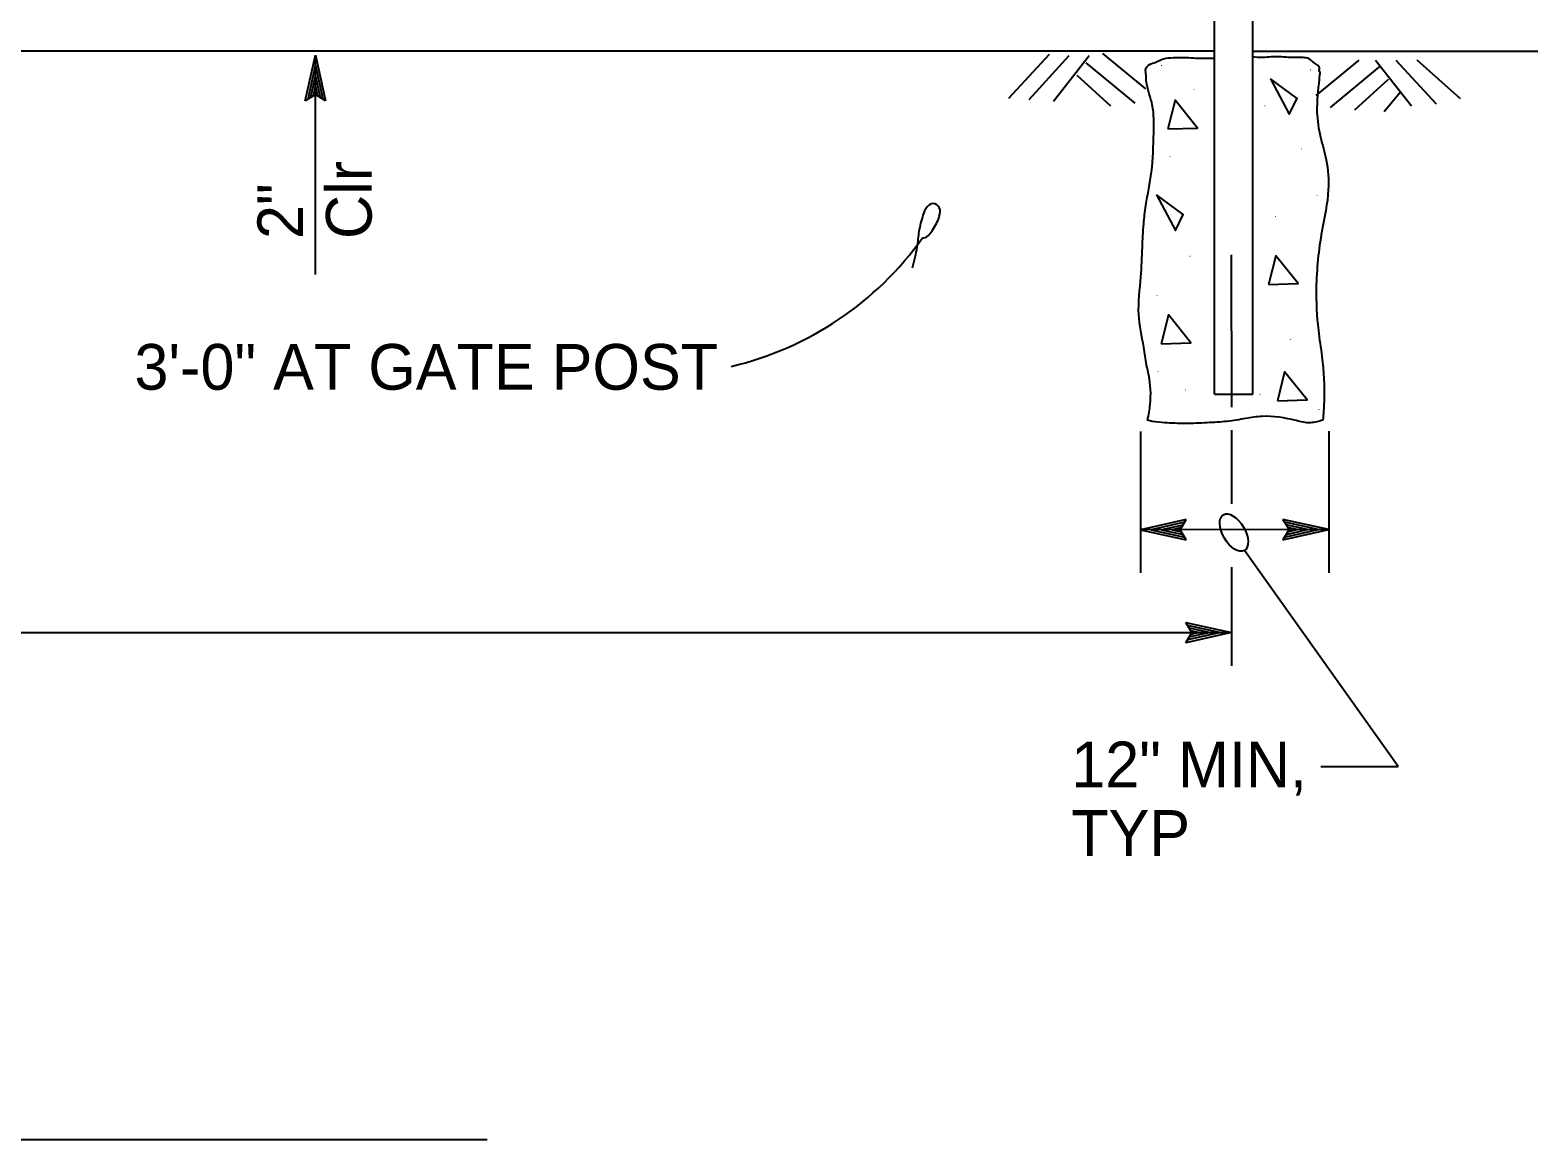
# Model space of a CAD drawing. Extents: x -121933 to -117742, y -103160 to -100084.
# Drawn here: x -120965.9 to -120768, y -102524.1 to -102378.5 of the extents above; entities that cross this region are included whole.
import ezdxf

# ---------------------------------------------------------------- set-up
doc = ezdxf.new("R2010")
doc.units = 0
for name, color, linetype in [('G-MARK', 7, 'Continuous'), ('G-TEXT', 7, 'Continuous'), ('Misc CnstDet(22)', 7, 'Continuous'), ('Nongeo Data(60)', 7, 'Continuous')]:
    doc.layers.add(name, color=color, linetype=linetype)

msp = doc.modelspace()

# ---------------------------------------------------------------- linework, layer by layer
at = {"layer": 'G-MARK'}
for p, q in [((-120928.4, -102410.53), (-120928.4, -102381.74)), ((-120820.14, -102431.16), (-120820.14, -102449.7)), ((-120795.42, -102431.12), (-120795.42, -102449.7)), ((-120795.42, -102444.03), (-120820.12, -102444.06)), ((-120786.31, -102475.15), (-120806.48, -102446.78)), ((-121220.62, -102457.55), (-120808.19, -102457.55)), ((-120796.44, -102475.15), (-120786.31, -102475.15))]:
    msp.add_line(p, q, dxfattribs=at)
for points in [[(-120808.21, -102407.98), (-120808.19, -102427.98)], [(-120808.19, -102430.98), (-120808.18, -102440.63)], [(-120808.18, -102448.96), (-120808.2, -102461.92)]]:
    msp.add_lwpolyline(points, dxfattribs=at)
msp.add_arc((-120883.78, -102380.7), 43.08, 283.3407, 324.4518, dxfattribs=at)
msp.add_ellipse((-120807.86, -102444.43), major_axis=(-1.38, 2.35), ratio=0.531478, dxfattribs=at)
msp.add_spline([(-120848.73, -102405.74), (-120848.4, -102405.69), (-120847.42, -102404.71), (-120846.53, -102402.93), (-120846.53, -102401.77), (-120847.33, -102401.24), (-120848.13, -102401.68), (-120848.67, -102402.75), (-120849.2, -102404.89), (-120849.47, -102406.94), (-120850.09, -102409.7)], degree=3, dxfattribs=at)
at = {"layer": 'G-TEXT'}
for p, q in [((-120929.74, -102387.74), (-120928.4, -102381.74)), ((-120929.38, -102387.53), (-120928.4, -102383.12)), ((-120928.4, -102381.74), (-120928.4, -102381.74)), ((-120928.4, -102381.74), (-120927.07, -102387.74)), ((-120928.4, -102383.13), (-120927.43, -102387.51)), ((-120929.02, -102387.29), (-120928.4, -102384.5)), ((-120928.4, -102384.5), (-120927.78, -102387.33)), ((-120928.4, -102386.94), (-120929.74, -102387.74)), ((-120928.68, -102387.12), (-120928.4, -102385.89)), ((-120928.4, -102385.89), (-120928.13, -102387.1)), ((-120927.07, -102387.74), (-120928.4, -102386.94)), ((-120929.74, -102387.74), (-120929.74, -102387.74)), ((-120927.07, -102387.74), (-120927.07, -102387.74)), ((-120814.12, -102442.71), (-120820.12, -102444.06)), ((-120820.12, -102444.06), (-120820.12, -102444.06)), ((-120820.12, -102444.06), (-120814.11, -102445.38)), ((-120814.33, -102443.07), (-120818.74, -102444.06)), ((-120818.72, -102444.06), (-120814.35, -102445.02)), ((-120814.57, -102443.43), (-120817.35, -102444.05)), ((-120817.35, -102444.05), (-120814.53, -102444.68)), ((-120814.74, -102443.77), (-120815.97, -102444.05)), ((-120815.97, -102444.05), (-120814.76, -102444.32)), ((-120814.92, -102444.05), (-120814.12, -102442.71)), ((-120814.11, -102445.38), (-120814.92, -102444.05)), ((-120814.12, -102442.71), (-120814.12, -102442.71)), ((-120795.42, -102444.03), (-120801.43, -102442.71)), ((-120801.43, -102442.71), (-120801.43, -102442.71)), ((-120801.43, -102442.71), (-120800.62, -102444.04)), ((-120801.42, -102445.38), (-120795.42, -102444.03)), ((-120800.62, -102444.04), (-120801.42, -102445.38)), ((-120801.21, -102445.02), (-120796.8, -102444.03)), ((-120796.82, -102444.03), (-120801.19, -102443.07)), ((-120798.19, -102444.04), (-120801.01, -102443.41)), ((-120800.97, -102444.66), (-120798.19, -102444.04)), ((-120800.8, -102444.32), (-120799.57, -102444.04)), ((-120799.57, -102444.04), (-120800.78, -102443.77)), ((-120795.42, -102444.03), (-120795.42, -102444.03)), ((-120814.11, -102445.38), (-120814.11, -102445.38)), ((-120801.42, -102445.38), (-120801.42, -102445.38)), ((-120813.39, -102457.55), (-120814.19, -102456.21)), ((-120814.19, -102456.21), (-120814.19, -102456.21)), ((-120814.19, -102456.21), (-120808.19, -102457.55)), ((-120808.19, -102457.55), (-120814.19, -102458.88)), ((-120814.19, -102458.88), (-120813.39, -102457.55)), ((-120813.98, -102456.57), (-120809.57, -102457.55)), ((-120809.58, -102457.55), (-120813.96, -102458.52)), ((-120810.95, -102457.55), (-120813.78, -102458.17)), ((-120813.74, -102456.93), (-120810.95, -102457.55)), ((-120813.57, -102457.27), (-120812.34, -102457.55)), ((-120812.34, -102457.55), (-120813.54, -102457.81)), ((-120808.19, -102457.55), (-120808.19, -102457.55)), ((-120814.19, -102458.88), (-120814.19, -102458.88))]:
    msp.add_line(p, q, dxfattribs=at)
at = {"layer": 'Misc CnstDet(22)'}
msp.add_line((-120905.86, -102524.14), (-121238.29, -102524.14), dxfattribs=at)
at = {"layer": 'Nongeo Data(60)'}
for p, q in [((-120810.39, -102426.24), (-120810.39, -102366.89)), ((-120805.39, -102426.24), (-120805.39, -102366.89)), ((-120810.39, -102381.24), (-121014.39, -102381.24)), ((-120805.39, -102381.24), (-120767.97, -102381.24)), ((-120832.13, -102381.68), (-120837.43, -102387.44)), ((-120829.51, -102381.84), (-120834.8, -102387.6)), ((-120826.84, -102381.84), (-120831.54, -102387.82)), ((-120827.31, -102382.74), (-120820.86, -102388.04)), ((-120825.11, -102381.55), (-120819.47, -102386.19)), ((-120791.46, -102382.43), (-120797.09, -102387.07)), ((-120789.26, -102382.41), (-120784.56, -102388.39)), ((-120786.6, -102382.41), (-120781.3, -102388.16)), ((-120783.85, -102382.37), (-120778.15, -102387.44)), ((-120828.48, -102384.39), (-120824.08, -102388.39)), ((-120788.8, -102383.3), (-120795.24, -102388.61)), ((-120787.62, -102384.95), (-120792.02, -102388.96)), ((-120786.06, -102386.67), (-120788.12, -102389.2)), ((-120810.39, -102426.24), (-120805.39, -102426.24)), ((-120810.39, -102426.24), (-120805.39, -102426.24)), ((-120810.39, -102426.24), (-120805.39, -102426.24))]:
    msp.add_line(p, q, dxfattribs=at)
for points in [[(-120803.06, -102384.85), (-120800.59, -102389.5), (-120799.56, -102387.43)], [(-120816.54, -102391.43), (-120812.64, -102391.32), (-120815.59, -102387.66)], [(-120818.01, -102400.1), (-120815.54, -102404.75), (-120814.52, -102402.68)], [(-120803.31, -102411.86), (-120799.41, -102411.75), (-120802.36, -102408.09)], [(-120817.4, -102419.63), (-120813.5, -102419.52), (-120816.46, -102415.86)], [(-120802.16, -102427.11), (-120798.26, -102427), (-120801.21, -102423.34)]]:
    msp.add_lwpolyline(points, close=True, dxfattribs=at)
for points in [[(-120819.41, -102384.14), (-120819.42, -102383.53), (-120818.99, -102383.02), (-120818.13, -102382.67), (-120817.09, -102382.24), (-120815.8, -102382.07), (-120813.83, -102382.07), (-120812.54, -102382.16), (-120811.16, -102382.16), (-120810.56, -102382.16)], [(-120796.58, -102383.88), (-120796.62, -102383.88), (-120796.62, -102383.53), (-120796.8, -102383.1), (-120797.31, -102382.76), (-120798, -102382.24), (-120798.77, -102382.07), (-120800.41, -102382.07), (-120801.61, -102381.98), (-120802.99, -102381.98), (-120804.02, -102382.07), (-120805.48, -102381.98)], [(-120819.19, -102429.66), (-120818.85, -102427.58), (-120819.04, -102423.75), (-120819.32, -102422.44), (-120819.7, -102420.1), (-120820.35, -102415.79), (-120820.07, -102410.84), (-120819.88, -102407), (-120819.7, -102403.91), (-120819.42, -102401.48), (-120818.67, -102397.08), (-120818.39, -102391.94), (-120818.57, -102388.29), (-120819.32, -102385.39), (-120819.41, -102384.14)], [(-120796.58, -102383.88), (-120796.68, -102384.92), (-120796.96, -102389.22), (-120796.5, -102392.5), (-120795.75, -102395.49), (-120795.47, -102399.42), (-120796.31, -102404.85), (-120797.06, -102412.33), (-120796.78, -102417.85), (-120796.31, -102421.31), (-120796.03, -102427.21), (-120796.19, -102429.66)], [(-120796.19, -102429.66), (-120797.81, -102430.01), (-120799.68, -102429.73), (-120804.17, -102429.17), (-120806.32, -102429.45), (-120808.75, -102429.83), (-120811.37, -102430.01), (-120814.27, -102430.11), (-120816.98, -102430.01), (-120818.57, -102429.83), (-120819.19, -102429.66)]]:
    msp.add_spline(points, degree=3, dxfattribs=at)

# ---------------------------------------------------------------- texts
at = {"layer": 'Misc CnstDet(22)'}
for s, p in [('3\'-0" AT GATE POST', (-120952.17, -102425.67)), ('12" MIN,', (-120829.21, -102477.86)), ('TYP', (-120829.21, -102486.86))]:
    msp.add_text(s, height=6, dxfattribs=at).set_placement(p)
at = {"layer": 'Nongeo Data(60)'}
for s, height, rotation, p in [('.', 0.8, 93.0685, (-120817.28, -102383.26)), ('.', 0.8, 93.0685, (-120797.75, -102383.83)), ('.', 0.8, 93.0685, (-120812.99, -102386.42)), ('.', 0.8, 93.0685, (-120803.74, -102388.56)), ('.', 0.8, 93.0685, (-120816.15, -102395.22)), ('.', 0.8, 93.0685, (-120798.9, -102394.19)), ('Clr', 6, 90, (-120921.03, -102405.89)), ('2"', 6, 90, (-120930.03, -102405.89)), ('.', 0.8, 93.0685, (-120796.86, -102400.3)), ('.', 0.8, 93.0685, (-120802.35, -102403.11)), ('.', 0.8, 93.0685, (-120813.57, -102408.29)), ('.', 0.8, 93.0685, (-120817.88, -102413.47)), ('.', 0.8, 93.0685, (-120800.34, -102419.22)), ('.', 0.8, 93.0685, (-120817.73, -102423.44)), ('.', 0.8, 93.0685, (-120814.14, -102425.84)), ('.', 0.8, 93.0685, (-120804.36, -102426.41)), ('.', 0.8, 93.0685, (-120796.63, -102428.41))]:
    msp.add_text(s, height=height, rotation=rotation, dxfattribs=at).set_placement(p)

doc.saveas('drawing.dxf')
